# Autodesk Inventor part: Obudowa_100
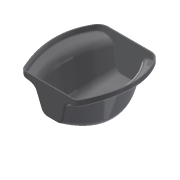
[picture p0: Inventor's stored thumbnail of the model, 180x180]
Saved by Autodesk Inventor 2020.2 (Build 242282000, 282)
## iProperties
Created: 2010-12
Part Number: Obudowa_100
Document SubType Name: Modeling
Designer: F.Stasiak
Density: 1 g/cm^3
Material: Ogólny
Appearance: Gładki - średnioszary
Manager: www.cadconsulting.pl
Company: Fabian Stasiak CAD Consulting
Author: F.Stasiak
Subject: Zbiór ćwiczeń. Autodesk Inventor 2020. Kurs podstawowy
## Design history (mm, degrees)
sketch "Szkic2"
  geometry: L1 (125, 116.28)-(97.749, 108.978); L2 (76.536, 87.765)-(58.978, 22.235); L3 (30, 0)-(-30, 0); L4 (-58.978, 22.235)-(-76.536, 87.765); L5 (-97.749, 108.978)-(-125, 116.28); L6 (0, 0)-(0, 100); A1 r 30 centre (105.514, 80) between (97.749, 108.978) and (76.536, 87.765); A2 r 30 centre (30, 30) between (30, 0) and (58.978, 22.235); A3 r 30 centre (-30, 30) between (-58.978, 22.235) and (-30, 0); A4 r 30 centre (-105.514, 80) between (-76.536, 87.765) and (-97.749, 108.978); 1 further point
  constraints: 12 end point, 8 point on circle, 5 tangent, 4 centre point, 2 perpendicular, 1 coincident, 1 equal length, 1 horizontal, 1 midpoint, 4 other
  dimensions: "d4" = 30 radius of A2; "d5" = 60 distance of L3.start L3.end; "d6" = 15 deg angle of L6 L4; "d7" = 80 distance from line of A4.centre L3; "d8" = 250 distance of L5.end L1.start; "d9" = 30 radius of A1 (= d4); "d11" = 100 distance of L6.start L6.end
node "Płaszczyzna konstrukcyjna1"
sketch "Szkic3"
  geometry: L1 (101.716, 113.636)-(71.626, 109.41); L2 (51.6, 93.092)-(34.744, 45.875); L3 (13.003, 30.552)-(-13.003, 30.552); L4 (-34.744, 45.875)-(-51.6, 93.092); L5 (-71.626, 109.41)-(-99.818, 113.37); L6 (0, 0)-(0, 100) reference; A1 r 24.948 centre (75.095, 84.704) between (71.626, 109.41) and (51.6, 93.092); A2 r 23.085 centre (13.003, 53.637) between (13.003, 30.552) and (34.744, 45.875); A3 r 23.085 centre (-13.003, 53.637) between (-34.744, 45.875) and (-13.003, 30.552); A4 r 24.948 centre (-75.095, 84.704) between (-51.6, 93.092) and (-71.626, 109.41); 1 further point
  constraints: 10 end point, 8 point on circle, 7 tangent, 4 centre point, 1 horizontal, 1 midpoint, 1 point on line, 4 other
node "Płaszczyzna konstrukcyjna2"
sketch "Szkic4"
  geometry: L1 (101.716, 113.636)-(71.626, 109.41) reference; L2 (51.6, 93.092)-(34.744, 45.875) reference; L3 (13.003, 30.552)-(-13.003, 30.552) reference; L4 (-34.744, 45.875)-(-51.6, 93.092) reference; L5 (-71.626, 109.41)-(-99.818, 113.37) reference; A1 r 24.948 centre (75.095, 84.704) between (71.626, 109.41) and (51.6, 93.092) reference; A2 r 23.085 centre (13.003, 53.637) between (13.003, 30.552) and (34.744, 45.875) reference; A3 r 23.085 centre (-13.003, 53.637) between (-34.744, 45.875) and (-13.003, 30.552) reference; A4 r 24.948 centre (-75.095, 84.704) between (-51.6, 93.092) and (-71.626, 109.41) reference; 1 further point
feature "PowWyciągnięciaZłożonego1" sketch "Szkic4" dims "d14" = 0, "d15" = 90 deg, "d16" = 0, "d17" = 90 deg, "d18" = 0, "d19" = 90 deg
sketch "Szkic5"
  geometry: L1 (101.716, 113.636)-(71.626, 109.41) reference; L2 (51.6, 93.092)-(34.744, 45.875) reference; L3 (13.003, 30.552)-(-13.003, 30.552) reference; L4 (-34.744, 45.875)-(-51.6, 93.092) reference; L5 (-71.626, 109.41)-(-99.818, 113.37) reference; L6 (101.716, 113.636)-(101.716, 138.636); L7 (101.716, 138.636)-(-99.818, 138.636); L8 (-99.818, 138.636)-(-99.818, 113.37); A1 r 24.948 centre (75.095, 84.704) between (71.626, 109.41) and (51.6, 93.092) reference; A2 r 23.085 centre (13.003, 53.637) between (13.003, 30.552) and (34.744, 45.875) reference; A3 r 23.085 centre (-13.003, 53.637) between (-34.744, 45.875) and (-13.003, 30.552) reference; A4 r 24.948 centre (-75.095, 84.704) between (-51.6, 93.092) and (-71.626, 109.41) reference; 1 further point
  constraints: 6 end point, 2 perpendicular, 1 parallel
  dimensions: "d20" = 25 distance of L1.start L6.end
feature "Zamknij obwiednię1" sketch "Szkic5"
sketch "Szkic6"
  geometry: L1 (-71.626, 109.41)-(-99.818, 113.37) reference; L2 (-34.744, 45.875)-(-51.6, 93.092) reference; L3 (13.003, 30.552)-(-13.003, 30.552) reference; L4 (51.6, 93.092)-(34.744, 45.875) reference; L5 (101.716, 113.636)-(71.626, 109.41) reference; L6 (-99.818, 138.636)-(101.716, 138.636) reference; L7 (-99.818, 138.636)-(-99.818, 113.37); L8 (101.716, 138.636)-(101.716, 113.636); A1 r 24.948 centre (-75.095, 84.704) between (-51.6, 93.092) and (-71.626, 109.41) reference; A2 r 23.085 centre (-13.003, 53.637) between (-34.744, 45.875) and (-13.003, 30.552) reference; A3 r 23.085 centre (13.003, 53.637) between (13.003, 30.552) and (34.744, 45.875) reference; A4 r 24.948 centre (75.095, 84.704) between (71.626, 109.41) and (51.6, 93.092) reference; 1 further point
  constraints: 4 end point, 1 parallel, 1 perpendicular
feature "Zamknij obwiednię2" sketch "Szkic6"
node "Płaszczyzna konstrukcyjna3"
feature "Zszyj powierzchnię1"
node "Płaszczyzna konstrukcyjna4"
feature "Podział1"
node "Płaszczyzna konstrukcyjna5"
feature "Podział2"
fillet "Zaokrąglenie4" dims "d37" = 40
fillet "Zaokrąglenie5" dims "d38" = 20
fillet "Zaokrąglenie6" dims "d39" = 10
feature "Skorupa1" dims "d34" = 4
node "Bryła1"
body "Srf1"
body "Srf2"
body "Srf3"
sketch "Szkic7"
  geometry: L1 (0, 0)-(201.534, 0) reference; L2 (0, 300)-(201.534, 300) reference; 1 further point
  constraints: 2 vertical alignment
body "Srf4"
body "Srf5"
body "Srf6"
feature "Zamknij obwiednię3"
feature "Zamknij obwiednię4" dims "d21" = 0, "d22" = 0, "d23" = 0, "d24" = 0, "d25" = 0
feature "Zamknij obwiednię5" dims "d26" = 0, "d27" = 0, "d28" = 0, "d29" = 0, "d30" = 0
other parameters: "d35" = 95 deg, "d36" = -95 deg
